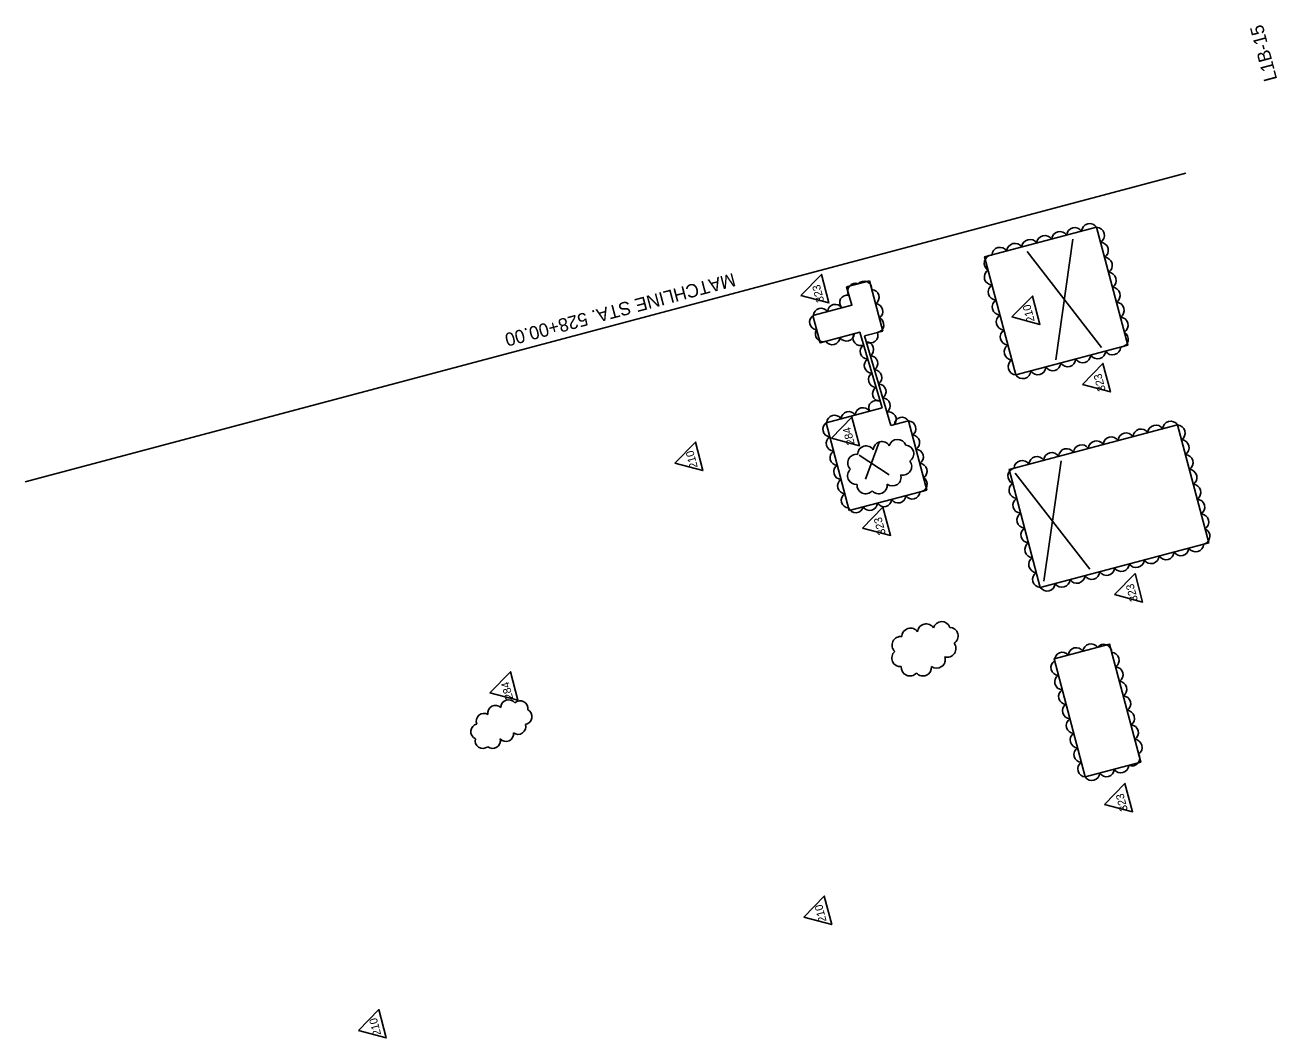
# Model space of a CAD drawing. Extents: x 930394 to 931451, y 627795 to 629076.
# Drawn here: x 930394 to 931144, y 628469 to 629076 of the extents above; entities that cross this region are included whole.
import ezdxf

# ---------------------------------------------------------------- set-up
doc = ezdxf.new("R2010")
doc.units = 0
for name, color, linetype in [('Cloud_dp', 7, 'Continuous'), ('MatchLines_dp', 7, 'Continuous'), ('NonPlottingEle_dp', 7, 'Continuous'), ('TextShtNo', 7, 'Continuous')]:
    doc.layers.add(name, color=color, linetype=linetype)

msp = doc.modelspace()

# ---------------------------------------------------------------- linework, layer by layer
at = {"layer": 'Cloud_dp'}
for p, q in [((931011.76, 628875.86), (931022.04, 628948.03)), ((931039.22, 628883.13), (930994.59, 628940.76)), ((930897.7, 628804.21), (930905.89, 628826.47)), ((930911.9, 628806.81), (930894.01, 628818.66)), ((931004.65, 628743.01), (931014.93, 628815.18)), ((931032.11, 628750.28), (930987.47, 628807.91))]:
    msp.add_line(p, q, dxfattribs=at)
for points in [[(930859.06, 628914.36), (930875.81, 628909.87), (930871.29, 628926.94)], [(930985.51, 628901.46), (931002.26, 628896.98), (930997.74, 628914.04)], [(931027.76, 628861), (931044.51, 628856.52), (931040, 628873.58)], [(930877.34, 628828.77), (930894.09, 628824.29), (930889.57, 628841.35)], [(930783.51, 628813.85), (930800.26, 628809.37), (930795.74, 628826.43)], [(930895.96, 628774.95), (930912.71, 628770.47), (930908.19, 628787.53)], [(931047.07, 628735.02), (931063.82, 628730.54), (931059.31, 628747.6)], [(930672.61, 628676.17), (930689.36, 628671.69), (930684.85, 628688.75)], [(931041.03, 628609.29), (931057.78, 628604.81), (931053.26, 628621.87)], [(930860.73, 628541.71), (930877.48, 628537.23), (930872.96, 628554.29)], [(930593.74, 628473.71), (930610.49, 628469.23), (930605.97, 628486.29)]]:
    msp.add_lwpolyline(points, close=True, dxfattribs=at)
for centre, radius, start, end in [((931032.16, 628952.61), 4.87, 32.32565, 177.32565), ((931005.23, 628945.48), 4.87, 32.32565, 177.32565), ((931014.21, 628947.85), 4.87, 32.32565, 177.32565), ((931023.18, 628950.23), 4.87, 32.32565, 177.32565), ((931036.04, 628950.35), 4.87, 302.32565, 87.32565), ((930978.31, 628938.35), 4.87, 32.32565, 177.32565), ((930987.28, 628940.73), 4.87, 32.32565, 177.32565), ((930996.26, 628943.1), 4.87, 32.32565, 177.32565), ((931038.42, 628941.37), 4.87, 302.32565, 87.32565), ((930973.76, 628933.72), 4.86, 93.69732, 238.69732), ((931040.79, 628932.4), 4.87, 302.32565, 87.32565), ((930973.83, 628925.45), 4.87, 122.32565, 267.32565), ((931043.17, 628923.42), 4.87, 302.32565, 87.32565), ((930891.65, 628917.07), 4.61, 67.77575, 212.77575), ((930896.91, 628918.35), 4.61, 354.77207, 139.77207), ((930976.21, 628916.48), 4.87, 122.32565, 267.32565), ((931045.54, 628914.45), 4.87, 302.32565, 87.32565), ((930886.86, 628910.05), 4.61, 78.56599, 223.56599), ((930901.29, 628913.33), 4.61, 302.32565, 87.32565), ((930978.58, 628907.5), 4.87, 122.32565, 267.32565), ((930871.11, 628902.15), 4.61, 32.32565, 177.32565), ((930879.62, 628904.4), 4.61, 32.32565, 177.32565), ((930903.54, 628904.82), 4.61, 302.32565, 87.32565), ((931047.92, 628905.47), 4.87, 302.32565, 87.32565), ((930868.83, 628898.38), 4.61, 120.18884, 265.18884), ((930904.08, 628896.74), 4.61, 280.24186, 65.24186), ((930980.96, 628898.53), 4.87, 122.32565, 267.32565), ((931050.29, 628896.5), 4.87, 302.32565, 87.32565), ((930872.27, 628891.21), 4.61, 146.14385, 291.14385), ((930877.83, 628889.38), 4.61, 212.32565, 357.32565), ((930886.33, 628891.63), 4.61, 212.32565, 357.32565), ((930894.82, 628888.92), 4.61, 147.29855, 292.29855), ((930900.61, 628890.5), 4.61, 236.54991, 21.54991), ((930983.33, 628889.56), 4.87, 122.32565, 267.32565), ((931050.37, 628888.23), 4.86, 273.69732, 58.69732), ((930899.14, 628880.83), 4.61, 123.88815, 268.88815), ((930897.98, 628882.05), 4.61, 303.88815, 88.88815), ((930985.71, 628880.58), 4.87, 122.32565, 267.32565), ((931036.85, 628881.22), 4.87, 212.32565, 357.32565), ((931045.82, 628883.6), 4.87, 212.32565, 357.32565), ((930901.62, 628872.39), 4.61, 123.88815, 268.88815), ((930900.46, 628873.61), 4.61, 303.88815, 88.88815), ((930988.09, 628871.61), 4.87, 122.32565, 267.32565), ((931009.92, 628874.1), 4.87, 212.32565, 357.32565), ((931018.9, 628876.47), 4.87, 212.32565, 357.32565), ((931027.87, 628878.85), 4.87, 212.32565, 357.32565), ((930904.11, 628863.95), 4.61, 123.88815, 268.88815), ((930902.94, 628865.17), 4.61, 303.88815, 88.88815), ((930991.97, 628869.35), 4.87, 212.32565, 357.32565), ((931000.95, 628871.72), 4.87, 212.32565, 357.32565), ((930906.59, 628855.51), 4.61, 123.88815, 268.88815), ((930905.42, 628856.73), 4.61, 303.88815, 88.88815), ((930904.22, 628846.89), 4.61, 60.34929, 205.34929), ((930907.91, 628848.28), 4.61, 303.88815, 88.88815), ((930887.65, 628840.2), 4.61, 32.32565, 177.32565), ((930896.15, 628842.45), 4.61, 32.32565, 177.32565), ((930911.56, 628839.97), 4.61, 318.61069, 103.61069), ((930876.8, 628834.14), 4.61, 119.32611, 264.32611), ((930879.14, 628837.95), 4.61, 32.32565, 177.32565), ((930919.63, 628836.71), 4.61, 32.32565, 177.32565), ((930923.31, 628834.57), 4.61, 302.32565, 87.32565), ((931071.75, 628831.82), 4.83, 32.32565, 177.32565), ((931080.65, 628834.17), 4.83, 32.32565, 177.32565), ((931084.51, 628831.93), 4.83, 302.32565, 87.32565), ((930878.81, 628825.65), 4.61, 122.32565, 267.32565), ((930925.56, 628826.06), 4.61, 302.32565, 87.32565), ((931045.04, 628824.75), 4.83, 32.32565, 177.32565), ((931053.94, 628827.1), 4.83, 32.32565, 177.32565), ((931062.85, 628829.46), 4.83, 32.32565, 177.32565), ((930881.06, 628817.15), 4.61, 122.32565, 267.32565), ((930898.12, 628818.99), 5.17, 33.90672, 178.90672), ((930907.57, 628821.59), 5.17, 31.82335, 176.82335), ((930916.93, 628822.92), 5.17, 19.39709, 164.39709), ((930921.53, 628819.48), 5.17, 301.91699, 86.91699), ((930927.81, 628817.56), 4.61, 302.32565, 87.32565), ((931018.33, 628817.68), 4.83, 32.32565, 177.32565), ((931027.23, 628820.03), 4.83, 32.32565, 177.32565), ((931036.14, 628822.39), 4.83, 32.32565, 177.32565), ((931086.86, 628823.03), 4.83, 302.32565, 87.32565), ((930892.26, 628813.97), 5.17, 82.1992, 227.1992), ((930920.24, 628811.85), 5.17, 253.88267, 38.88267), ((930930.07, 628809.05), 4.61, 302.32565, 87.32565), ((930991.62, 628810.61), 4.83, 32.32565, 177.32565), ((931000.53, 628812.96), 4.83, 32.32565, 177.32565), ((931009.43, 628815.32), 4.83, 32.32565, 177.32565), ((931089.22, 628814.13), 4.83, 302.32565, 87.32565), ((930883.31, 628808.65), 4.61, 122.32565, 267.32565), ((930892.13, 628806.27), 5.17, 130.9028, 275.9028), ((930913.88, 628805.32), 5.17, 232.60729, 17.60729), ((930987.86, 628806.13), 4.82, 102.66925, 247.66925), ((931091.58, 628805.22), 4.83, 302.32565, 87.32565), ((930885.56, 628800.14), 4.61, 122.32565, 267.32565), ((930897.8, 628800.62), 5.16, 174.31574, 319.31574), ((930905.6, 628800.66), 5.17, 221.16971, 6.16971), ((930930.11, 628801.23), 4.61, 273.38739, 58.38739), ((930988.61, 628797.58), 4.83, 122.32565, 267.32565), ((931093.93, 628796.32), 4.83, 302.32565, 87.32565), ((930887.81, 628791.64), 4.61, 122.32565, 267.32565), ((930908.77, 628792.34), 4.61, 212.32565, 357.32565), ((930917.27, 628794.59), 4.61, 212.32565, 357.32565), ((930925.78, 628796.84), 4.61, 212.32565, 357.32565), ((930990.96, 628788.68), 4.83, 122.32565, 267.32565), ((931096.29, 628787.42), 4.83, 302.32565, 87.32565), ((930891.89, 628788.71), 4.61, 201.36131, 346.36131), ((930900.27, 628790.09), 4.61, 212.32565, 357.32565), ((930993.32, 628779.78), 4.83, 122.32565, 267.32565), ((931098.65, 628778.51), 4.83, 302.32565, 87.32565), ((930995.68, 628770.88), 4.83, 122.32565, 267.32565), ((931099.39, 628769.97), 4.82, 282.66925, 67.66925), ((930998.03, 628761.97), 4.83, 122.32565, 267.32565), ((931086.73, 628763.13), 4.83, 212.32565, 357.32565), ((931095.63, 628765.49), 4.83, 212.32565, 357.32565), ((931000.39, 628753.07), 4.83, 122.32565, 267.32565), ((931051.11, 628753.71), 4.83, 212.32565, 357.32565), ((931060.02, 628756.06), 4.83, 212.32565, 357.32565), ((931068.92, 628758.42), 4.83, 212.32565, 357.32565), ((931077.82, 628760.78), 4.83, 212.32565, 357.32565), ((931002.75, 628744.17), 4.83, 122.32565, 267.32565), ((931024.41, 628746.64), 4.83, 212.32565, 357.32565), ((931033.31, 628748.99), 4.83, 212.32565, 357.32565), ((931042.21, 628751.35), 4.83, 212.32565, 357.32565), ((931006.6, 628741.93), 4.83, 212.32565, 357.32565), ((931015.5, 628744.28), 4.83, 212.32565, 357.32565), ((930934.09, 628712.35), 5.17, 31.82335, 176.82335), ((930943.46, 628713.68), 5.17, 19.39709, 164.39709), ((930918.78, 628704.73), 5.17, 82.1992, 227.1992), ((930924.65, 628709.75), 5.17, 33.90672, 178.90672), ((930948.05, 628710.24), 5.17, 301.91699, 86.91699), ((930918.65, 628697.04), 5.17, 130.9028, 275.9028), ((930946.76, 628702.61), 5.17, 253.88267, 38.88267), ((931024.09, 628698.5), 4.72, 32.32565, 177.32565), ((931032.79, 628700.8), 4.72, 32.32565, 177.32565), ((931040.58, 628700.52), 4.72, 358.55232, 143.55232), ((930940.4, 628696.08), 5.17, 232.60729, 17.60729), ((931013.57, 628691.36), 4.72, 122.32565, 267.32565), ((931015.74, 628695.72), 4.71, 39.52891, 184.52891), ((931045.07, 628695.69), 4.72, 302.32565, 87.32565), ((930924.32, 628691.39), 5.16, 174.31574, 319.31574), ((930932.13, 628691.42), 5.17, 221.16971, 6.16971), ((931015.87, 628682.66), 4.72, 122.32565, 267.32565), ((931047.37, 628686.99), 4.72, 302.32565, 87.32565), ((931049.68, 628678.29), 4.72, 302.32565, 87.32565), ((930683.77, 628667.4), 4.61, 35.57457, 180.57457), ((930690.73, 628666.78), 4.61, 349.23692, 134.23692), ((931018.17, 628673.96), 4.72, 122.32565, 267.32565), ((931051.98, 628669.59), 4.72, 302.32565, 87.32565), ((930669.02, 628659.22), 4.61, 58.30599, 203.30599), ((930675.96, 628664.03), 4.61, 46.10262, 191.10262), ((930693.21, 628661.79), 4.61, 278.6372, 63.6372), ((931020.48, 628665.26), 4.72, 122.32565, 267.32565), ((931054.28, 628660.89), 4.72, 302.32565, 87.32565), ((930665.72, 628652.88), 4.61, 101.67952, 246.67952), ((930689.51, 628655.84), 4.61, 232.5707, 17.5707), ((931022.78, 628656.56), 4.72, 122.32565, 267.32565), ((931056.58, 628652.19), 4.72, 302.32565, 87.32565), ((930668.33, 628647.42), 4.61, 164.49119, 309.49119), ((930674.24, 628647.38), 4.61, 229.80899, 14.80899), ((930682.13, 628651.63), 4.61, 221.79772, 6.79772), ((931025.08, 628647.85), 4.72, 122.32565, 267.32565), ((931027.39, 628639.15), 4.72, 122.32565, 267.32565), ((931058.89, 628643.48), 4.72, 302.32565, 87.32565), ((931029.69, 628630.45), 4.72, 122.32565, 267.32565), ((931057.41, 628636.99), 4.72, 247.02846, 32.02846), ((931033.46, 628628.26), 4.72, 212.32565, 357.32565), ((931042.16, 628630.57), 4.72, 212.32565, 357.32565), ((931050.86, 628632.87), 4.72, 212.32565, 357.32565)]:
    msp.add_arc(centre, radius, start, end, dxfattribs=at)
at = {"layer": 'MatchLines_dp'}
msp.add_lwpolyline([(931089.74, 628987.65), (930741.83, 628895.14), (930393.92, 628802.63)], dxfattribs=at)
at = {"layer": 'NonPlottingEle_dp'}
for p, q in [((930900.13, 628923.12), (930886.33, 628919.46)), ((930908.09, 628893.04), (930900.13, 628923.12)), ((930897.05, 628890.12), (930908.09, 628893.04)), ((930912.86, 628836.35), (930897.05, 628890.12)), ((930907.66, 628846.93), (930874.09, 628838.05)), ((930874.09, 628838.05), (930888.02, 628785.41)), ((930923.53, 628839.18), (930912.86, 628836.35)), ((930934.5, 628797.71), (930923.53, 628839.18)), ((930888.02, 628785.41), (930934.5, 628797.71))]:
    msp.add_line(p, q, dxfattribs=at)
for points in [[(930987.86, 628866.74), (930969.15, 628937.44), (931036.27, 628955.21), (931054.98, 628884.51)], [(931002.52, 628739.34), (930983.81, 628810.04), (931084.73, 628836.75), (931103.44, 628766.06)], [(931029.47, 628625.74), (931010.76, 628696.44), (931044.01, 628705.24), (931062.72, 628634.54)]]:
    msp.add_lwpolyline(points, close=True, dxfattribs=at)
msp.add_lwpolyline([(930886.33, 628919.46), (930889.57, 628908.47), (930866.19, 628902.28), (930870.5, 628886.01), (930894.32, 628892.31), (930907.66, 628846.93)], dxfattribs=at)

# ---------------------------------------------------------------- texts
at = {"layer": 'Cloud_dp'}
for s, p in [('323', (930873.05, 628910.87)), ('210', (930999.22, 628899.03)), ('323', (931041.75, 628857.52)), ('284', (930891.3, 628825.4)), ('210', (930797.22, 628811.42)), ('323', (930909.95, 628771.47)), ('323', (931061.07, 628731.54)), ('284', (930686.57, 628672.8)), ('323', (931055.02, 628605.81)), ('210', (930874.44, 628539.28)), ('210', (930607.45, 628471.28))]:
    msp.add_text(s, height=4.799, rotation=104.82565, dxfattribs=at).set_placement(p)
at = {"layer": 'MatchLines_dp'}
msp.add_text('MATCHLINE STA. 528+00.00', height=8, rotation=194.89045, dxfattribs=at).set_placement((930818.49, 628927.94))
at = {"layer": 'TextShtNo'}
msp.add_text('L1B-15', height=8, rotation=104.82565, dxfattribs=at).set_placement((931144.59, 629043.92))

doc.saveas('drawing.dxf')
